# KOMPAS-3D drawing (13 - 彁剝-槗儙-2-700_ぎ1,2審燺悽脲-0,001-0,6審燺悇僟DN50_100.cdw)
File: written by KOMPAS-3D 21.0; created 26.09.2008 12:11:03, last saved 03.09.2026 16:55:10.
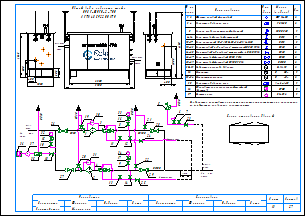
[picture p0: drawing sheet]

Sheets 1-2: A3, landscape

Document properties: Наименование: Макро:21; Автор: RaskoAdmin; Форматы листов документа: 2xA3; Полное имя файла: \\UR38nt01\Departments\КТО\КБ ПУРДГ\Заявки\Прайс-лист на типовые шкафы ГРПШ\ПРДГ_стандарт_20_03_2026\ПРДГ с РДГ(Н, В)\ПРДГ-ШУГО-2-700_до1,2МПа_Рвых-0,001-0,6МПа_РДГ_DN50_100.cdw

Title block, sheet 1: Наименование: Пункт учета газа / ПУГ-Ш-400-Р / ЛГТИ.485922.001ТУ; designation: ЛГТИ.03.4411141; sheet number: 1; Количество листов документа: 2; organisation: ООО "ЭЛЬСТЕР Газэлектроника"; Форматы листов документа: A3; stored path: C:\Рабочие документы\Компас\ПУГ\Схема.cdw; Разработал: Устинов; Проверил: Кошкин; Утвердил: Кошкин
Title block, sheet 2: sheet number: 2; stored path: D:\Рабочие документы\Заявки\ПУРДГ\ПУРДГ-ШУЭО-2-100-Р 4411220.cdw; designation, second copy: ЛГТИ.03.4411141-

Views: Вид 1, Вид 2
Referenced files: wcvoit.frw
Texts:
  Normal
  Общий вид и габариты шкафа
  ПРДГ-ШУГО-2-700
  Вход
  газа
  PDI
  Выход
  Р=     кПа
  DN100
  DN50
  DN20
  Импульс DN20
  ≥5DN
  HYSWLongFangSong
  Р=       МПа
  № на
  схеме
  Усл.
  обозн.
  Марка
  (модель)
  Кол.
  Фильтр газовый фланцевый
  ФГ 16-50
  Регулятор давления газа
  РДГ-50
  Клапан предохранительный сбросной
  КПС DN20
  Кран шаровой газовый латунный
  DN15
  Кран кнопочный VE-РАСКО-НЗ-1,6-G1/2-М20
  Кран шаровой "под приварку" штуцерный DN20 PN16
  Кран шаровой "под приварку" штуцерный п/п DN20 PN16
  Кран шаровой фланцевый DN50 PN16
  Кран шаровой фланцевый DN100 PN16
  Индикатор перепада давления
  Delta 15
  Манометр
  Манометр-напоромер
  0...     МПа
  0...     кПа
  Обогреватель газогорелочный шкафной
  (Эльтон")
  Счетчик газа
  Venio-A-15
  ОГШН
  BK-G1,6
  Схема открывания дверей
  Предприятие изготовитель может заменять комплектующие на аналогичные,
  не ухудшающие заявленных характеристик.
  Вход газа
  Выход газа
  logo-rasko-ge(1).png
  Должность
  Конструктор
  Фамилия
  Подпись
  Дата
  Согласовано
  Максимкин
  Лист
  Листов
  POLYLINE_STYLE_0.18_RGB_0_0_0
  POLYLINE_STYLE_0.50_RGB_0_0_0
  POLYLINE_STYLE_0.34_RGB_0_0_0
  PHANTOM_RGB_0_0_0_SC_1_THICK_0.18
  K5LT_THIN_RGB_0_0_0_THICK_0.18
  K5LT32769_RGB_0_0_0_THICK_0.18
  K5LT12_RGB_0_0_0_SC_1_THICK_0.18
  K5LT_DASHED_RGB_0_0_0_SC_1_THICK_0.18
  ACISOTGL_RGB_0_0_0_SC_0.8_THICK_0.25
  CONTINUOUS_RGB_0_127_31_THICK_0.3
  CONTINUOUS_RGB_0_0_255_THICK_0.35
  CONTINUOUS_RGB_255_0_0_THICK_0.35
  POLYLINE_STYLE_0.25_RGB_0_0_0
  CONTINUOUS_RGB_0_0_0_THICK_0.5
  POLYLINE_STYLE_0.35_RGB_0_0_255
  CONTINUOUS_RGB_0_0_0_THICK_0.4
  CONTINUOUS_RGB_0_0_0_THICK_0.35
  Без оформления
Dimensions and other numbers on the sheet: 1; 2; 3; 4; 5; 10; 27; 28; 29; 23; 8; 12; 19; 20; 21; 22; 25; 24; 30; 31; 15; 16; 32; 26; 6; 7; 11; 14; 13; 33; 9; 17; 34; 18; 35; 36; 37; 1, 2; 3, 4; 6-14; 15-17; 18-23; 24-25; 26-27; 28-29; 30-31; 33-34; 400; 1050; 500; 305; 2800; 1565; 3100; 1000; 4130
